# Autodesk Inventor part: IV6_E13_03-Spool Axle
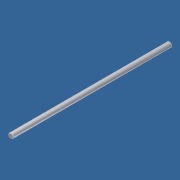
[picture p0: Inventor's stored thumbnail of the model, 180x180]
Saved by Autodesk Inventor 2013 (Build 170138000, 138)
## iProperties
Shininess: 64.0
Length Units: 11269
Angle Units: 11279
Time Units: 11290
Mass Units: 11286
Length Display Precision: 3
Angle Display Precision: 2
Compacted: True
Created: 2002-08
Part Number: IV6_E13_03-Spool Axle
Document SubType Name: Modeling
Designer: kalamea
Density: 1 g/cm^3
Material: Generic
Mass: 97.9187 g
Surface Area: 249.985 cm^2
Volume: 97.9187 cm^3
Density: 0.0
Volumn: 0.0
Area: 0.0
PropertySet Name: Model Information
Control State: 0
Master: False
Checked Out: False
DRAWING NUMBER: ME013-2007-PT
Author: kalamea
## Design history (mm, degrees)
sketch "Sketch1"
  geometry: C1 r 7.938 at (1.289, 5.158)
  constraints: 1 centre point
  dimensions: "d0" = 15.875 diameter of C1
extrude "Extrusion1" new body sketch "Sketch1" stored distance "d1" = 495.3; taper "d2" = 0 deg
chamfer "Chamfer1" distance "d3" = 1.5875; stored, may be unused: second distance "d4" = 1.5875, angle "d5" = 45 deg
body "Solid1"
